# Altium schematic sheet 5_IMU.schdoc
size 309 x 223 mm; Symbol: Sheet-Symbol_A4; Device: Sheet-Symbol_A4; @Project Name: BFMC_Power Board V2; @Page Count: 5; @Update Date: 2024-08-30; @Create Date: 2024-08-30; @Schematic Name: Balance_batt_protection_SolidState_4; @Page No: 5; @Page Name: IMU; Company: EasyEDA.com; Reviewed: EasyEDA; Version: V0.1; Page Size: A4; Part Number: JLCPCB-002; Drawn: EasyEDA; @Board Name: greater0603 Csample-3V3config; @Create Time: 09:44:13; @Update Time: 12:44:14
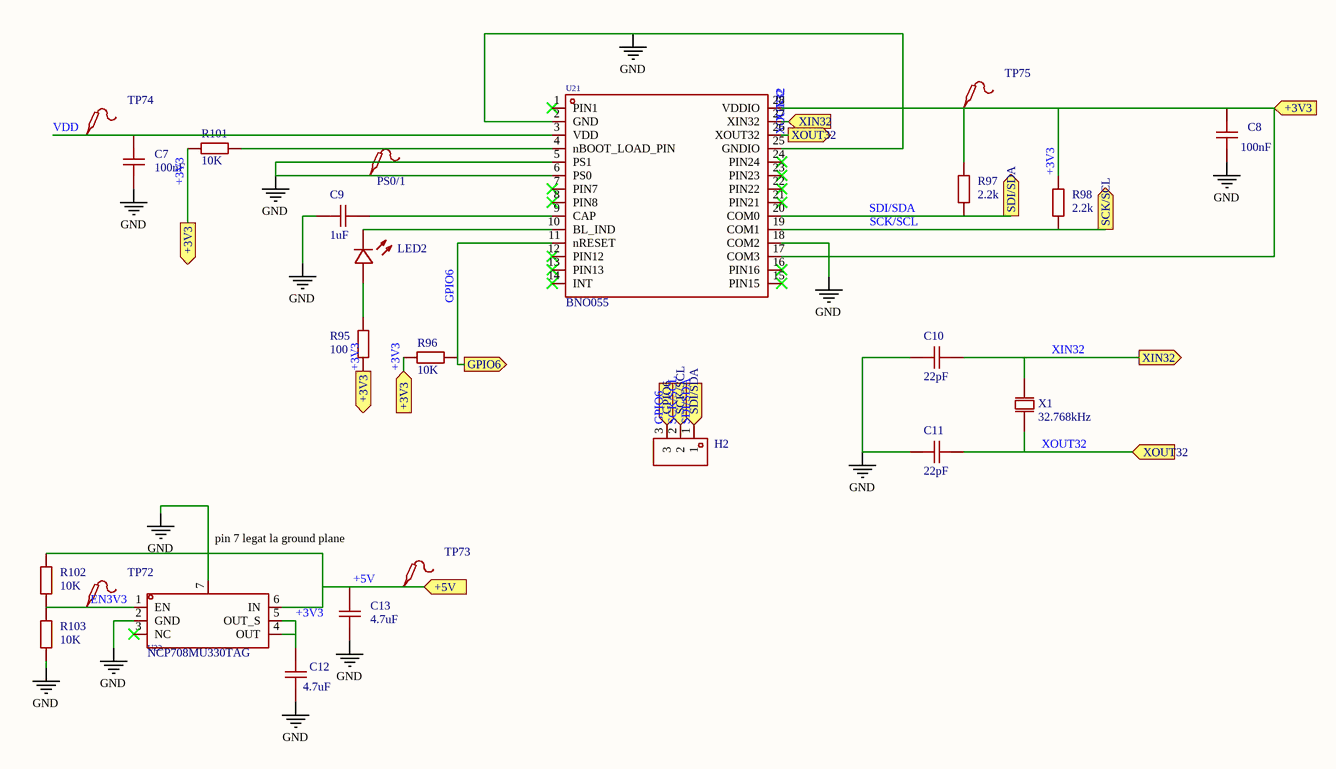
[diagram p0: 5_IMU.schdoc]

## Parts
C7  100nF  [Cbst2]  (value not drawn)
C8  100nF  [Cbst2]  (value not drawn)
C9  1uF  [C9]  (value not drawn)
C10  22pF  [C0603]  (value not drawn)
C11  22pF  [C0603]  (value not drawn)
C12  4.7uF  [C9]  (value not drawn)
C13  4.7uF  [C9]  (value not drawn)
H2  HDR-M_2.54_1x3P  [HDR-TH_3P-P2.54-V-M]  (value not drawn)
LED2  TLMS1100-GS08  [LED2 RED]  (value not drawn)
PS0/1  Test-Point  [Test-Point-0.5mm]  (value not drawn)
R95  100  [Rtrip]  (value not drawn)
R96  10K  [0805 dany2]  (value not drawn)
R97  2.2k  [0805 dany2]  (value not drawn)
R98  2.2k  [0805 dany2]  (value not drawn)
R101  10K  [0805 dany2]  (value not drawn)
R102  10K  [R0805_NEW]  (value not drawn)
R103  10K  [R0805_NEW]  (value not drawn)
TP72  Test-Point  [Test-Point-0.5mm]  (value not drawn)
TP73  Test-Point  [Test-Point-0.5mm]  (value not drawn)
TP74  Test-Point  [Test-Point-0.5mm]  (value not drawn)
TP75  Test-Point  [Test-Point-0.5mm]  (value not drawn)
U21  BNO055  [LGA-28_L5.2-W3.8-P0.50-BL]  (value not drawn)
U22  NCP708MU330TAG  [DFN-6_L3.0-W3.0-P0.95-LS3.1-BL-EP]  (value not drawn)
X1  32.768kHz  [OSC-SMD_2P-L1.6-W1.0]  (value not drawn)

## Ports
+3V3 (in), +3V3 (out), +5V (in), GPIO6 (in), GPIO6 (out), SCK/SCL (in), SCK/SCL (out), SDI/SDA (in), SDI/SDA (out), XIN32 (in), XIN32 (out), XOUT32 (in), XOUT32 (out)

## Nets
GND: C7.1 C8.2 C9.1 C10.2 C11.2 C12.1 C13.1 PS0/1.1 R103.2 U21.2(GND) U21.5(PS1) U21.6(PS0) U21.18(COM2) U21.25(GNDIO) U22.2(GND) U22.7(PAD)
+3V3: C8.1 C12.2 R95.1 R96.2 R97.1 R98.2 R101.1 TP75.1 U21.17(COM3) U21.28(VDDIO) U22.4(OUT) U22.5(OUT_S) ; port +3V3
+5V: C13.2 R102.1 TP73.1 U22.6(IN) ; port +5V
EN3V3: R102.2 R103.1 TP72.1 U22.1(EN)
GPIO6: H2.3 R96.1 U21.11(nRESET) ; port GPIO6
SCK/SCL: H2.2 R98.1 U21.19(COM1) ; port SCK/SCL
SDI/SDA: H2.1 R97.2 U21.20(COM0) ; port SDI/SDA
VDD: C7.2 TP74.1 U21.3(VDD)
XIN32: C10.1 U21.27(XIN32) X1.2(OSC2) ; port XIN32
XOUT32: C11.1 U21.26(XOUT32) X1.1(OSC1) ; port XOUT32
NetC9_2: C9.2 U21.9(CAP)
NetLED2_1: LED2.1(C) U21.10(BL_IND)
NetLED2_2: LED2.2(A) R95.2
NetR101_2: R101.2 U21.4(nBOOT_LOAD_PIN)

Not connected (* = marked no-connect by the designer): U21 1(PIN1)* 7(PIN7)* 8(PIN8)* 12(PIN12)* 13(PIN13)* 14(INT)* 15(PIN15)* 16(PIN16)* 21(PIN21)* 22(PIN22)* 23(PIN23)* 24(PIN24)*; U22 3(NC)*

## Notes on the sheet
- pin 7 legat la ground plane

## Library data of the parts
C7-C13 = CAP_0201: Symbol: CAP; Convert to PCB: yes
H2 = HDR-M_2.54_1x3P: Symbol: PZ254V-11-03P_C2937625; Convert to PCB: yes
LED2 = TLMS1100-GS08: Emitted Color:Red Forward Voltage (VF):2.1V Forward Voltage (VF):2.1V Forward Current:20mA Dominant Wavelength:633nm Dominant Wavelength:633nm Peak Wavelength:645nm Luminous Intensity:63mcd Luminous Intensity:63mcd Viewing Angle:160°; Manufacturer: VISHAY(威世); Add into BOM: yes; Emitted Color: Red; Forward Voltage (VF): 2.1V; Forward Current: 20mA; Dominant Wavelength: 633nm; Peak Wavelength: 645nm; Luminous Intensity: 63mcd; Viewing Angle: 160°
PS0/1 TP72-TP75 = Test-Point: Test Point 测试点; Add into BOM: yes
R95-R98 R101-R103 = Res_0201: Symbol: Res; Convert to PCB: yes
U21 = BNO055: Manufacturer: Bosch(博世); Add into BOM: yes
U22 = NCP708MU330TAG: Output Type: Maximum Input Voltage:5.5V Output Voltage:3.3V Output Voltage:3.3V MAX Output Current:1A Power Supply Rejection Ratio (PSRR):70dB@(1kHz) Dropout Voltage:330mV@(1A) Output Polarity:Positive electrode Number of Outputs:1; Manufacturer: onsemi(安森美); Add into BOM: yes; Maximum Input Voltage: 5.5V; Output Voltage: 3.3V; Number of Outputs: 1
X1 = ABS05-32.768kHz-T: Crystal Type:- Frequency: Normal temperature Frequency Tolerance:±20ppm Normal temperature Frequency Tolerance:±20ppm External load capacitor: Frequency Stability(Full temperature range):- Frequency Stability(Full temperature range):- Equivalent Series Re; Manufacturer: ABRACON; Add into BOM: yes; Normal temperature Frequency Tolerance: ±20ppm; Equivalent Series Resistance (ESR): 90kΩ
